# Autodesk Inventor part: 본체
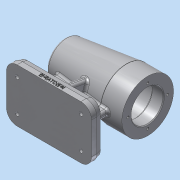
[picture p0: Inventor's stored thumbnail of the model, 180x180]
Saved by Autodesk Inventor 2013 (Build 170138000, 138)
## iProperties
Created: 2017-01
Part Number: 본체
Material: 알루미늄 6061
Document SubType Name: Modeling
Designer: dgall
Density: 2.71 g/cm^3
Mass: 795.17 g
Surface Area: 661.852 cm^2
Volume: 293.421 cm^3
Author: dgall
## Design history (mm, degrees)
sketch "스케치1"
  geometry: L1 (-56, 0)-(56, 0); L2 (56, 0)-(56, 34); L3 (56, 34)-(28, 34); L4 (28, 34)-(-52.27, 24.144); L5 (56, 21)-(41, 21); L6 (41, 21)-(41, 24); L7 (41, 24)-(-13, 24); L8 (-13, 24)-(-13, 21); L9 (-13, 21)-(-25, 21); L10 (-25, 21)-(-25, 17.5); L11 (-25, 17.5)-(-43, 17.5); L12 (-43, 17.5)-(-43, 16); L13 (-43, 16)-(-47, 16); L14 (-47, 16)-(-47, 10.5); L15 (-47, 10.5)-(-50, 10.5); L16 (-50, 10.5)-(-50, 0); A1 r 80 centre (24, 0) between (-52.27, 24.144) and (-56, 0); 2 further points
  constraints: 32 end point, 10 parallel, 3 perpendicular, 2 collinear, 2 point on circle, 2 point on line, 1 centre point, 1 coincident, 1 horizontal, 1 horizontal alignment, 1 midpoint
  dimensions: "d0" = 112 distance of L1.start L1.end; "d2" = 68 diameter of L3 L1; "d3" = 80 radius of A1; "d4" = 7 deg angle of L4 L3; "d5" = 28 distance of L2.end L3.end; "d6" = 48 diameter of L7 L1; "d7" = 42 diameter of L5 L1; "d9" = 35 diameter of L11 L1; "d10" = 32 diameter of L13 L1; "d11" = 21 diameter of L15 L1; "d12" = 15 distance of L5.start L5.end; "d13" = 54 distance of L6.end L7.end; "d14" = 3 distance of L14.end L15.end; "d15" = 4 distance of L12.end L13.end; "d16" = 18 distance of L10.end L11.end; "d17" = 12 distance of L8.end L9.end
revolve "회전1" sketch "스케치1" stored, may be unused: angle "d18" = 90 deg
node "작업 평면1"
sketch "스케치2"
  geometry: L1 (-56, 34)-(-56, -34) reference; L2 (-56, -35)-(56, -35); L3 (56, -35)-(56, 35); L4 (56, 35)-(-56, 35); L5 (-56, 35)-(-56, -35); 2 further points
  constraints: 8 end point, 2 parallel, 1 collinear, 1 horizontal, 1 horizontal alignment, 1 midpoint, 1 perpendicular
  dimensions: "d20" = 112 distance of L2.start L2.end; "d22" = 70 distance of L4.end L2.start
extrude "돌출1" join sketch "스케치2" distance "d23" = 7; taper "d24" = 0 deg
fillet "모깎기1" dims "d25" = 14
sketch "스케치3"
  geometry: L1 (42, 35)-(-42, 35) reference; L2 (-56, 21)-(-56, -21) reference; L3 (-42, -35)-(42, -35) reference; L4 (56, -21)-(56, 21) reference; A1 r 14 centre (42, 21) between (56, 21) and (42, 35) reference; A2 r 14 centre (-42, 21) between (-42, 35) and (-56, 21) reference; A3 r 14 centre (-42, -21) between (-56, -21) and (-42, -35) reference; A4 r 14 centre (42, -21) between (42, -35) and (56, -21) reference; 1 further point
extrude "돌출2" join sketch "스케치3" distance "d26" = 7; taper "d27" = -15 deg
sketch "스케치4"
  geometry: L1 (-74, -35)-(-74, 35) reference; L2 (-74, 35)-(-67, 35) reference; L3 (-67, 35)-(-60, 33.124) reference; L4 (-60, 33.124)-(-60, -33.124) reference; L5 (-60, -33.124)-(-67, -35) reference; L6 (-67, -35)-(-74, -35) reference; L7 (-18.211, 15.632)-(-60, 23); L8 (-18.211, -15.632)-(-60, -23); C1 r 30.562 at (0, 0) reference; A1 r 24 centre (0, 0) between (-18.211, 15.632) and (-18.211, -15.632) reference; 1 further point
  constraints: 4 end point, 2 point on circle, 2 point on line, 1 equal length
  dimensions: "d30" = 100 deg angle of L4 L7; "d31" = 100 deg angle of L4 L8; "d32" = 12 distance from line of L2 L7.end
extrude "돌출3" join sketch "스케치4" stored distance "d33" = 8; taper "d34" = 0 deg
sketch "스케치5"
  geometry: L1 (56, -74)-(-56, -74) reference; L2 (-56, -74)-(-56, -67) reference; L3 (-56, -67)-(-54.124, -60) reference; L4 (-54.124, -60)-(-4, -60) reference; L5 (-4, -60)-(-4, -30.071) reference; L6 (-4, -30.071)-(-52.27, -24.144) reference; L7 (-52.27, 24.144)-(28, 34) reference; L8 (28, 34)-(56, 34) reference; L9 (56, 34)-(56, 21) reference; L10 (56, 21)-(41, 21) reference; L11 (41, 21)-(41, 24) reference; L12 (41, 24)-(-13, 24) reference; L13 (-13, 24)-(-13, 21) reference; L14 (-13, 21)-(-25, 21) reference; L15 (-25, 21)-(-25, 17.5) reference; L16 (-25, 17.5)-(-43, 17.5) reference; L17 (-43, 17.5)-(-43, 16) reference; L18 (-43, 16)-(-47, 16) reference; L19 (-47, 16)-(-47, 10.5) reference; L20 (-47, 10.5)-(-50, 10.5) reference; L21 (-50, 10.5)-(-50, -10.5) reference; L22 (-50, -10.5)-(-47, -10.5) reference; L23 (-47, -10.5)-(-47, -16) reference; L24 (-47, -16)-(-43, -16) reference; L25 (-43, -16)-(-43, -17.5) reference; L26 (-43, -17.5)-(-25, -17.5) reference; L27 (-25, -17.5)-(-25, -21) reference; L28 (-25, -21)-(-13, -21) reference; L29 (-13, -21)-(-13, -24) reference; L30 (-13, -24)-(41, -24) reference; L31 (41, -24)-(41, -21) reference; L32 (41, -21)-(56, -21) reference; L33 (56, -21)-(56, -34) reference; L34 (56, -34)-(28, -34) reference; L35 (28, -34)-(4, -31.053) reference; L36 (4, -31.053)-(4, -60) reference; L37 (4, -60)-(54.124, -60) reference; L38 (54.124, -60)-(56, -67) reference; L39 (56, -67)-(56, -74) reference; L40 (-38, -25.896)-(-38, -60); L41 (38, -34)-(38, -60); A1 r 80 centre (24, 0) between (-52.27, 24.144) and (-52.27, -24.144) reference; 1 further point
  constraints: 4 end point, 4 point on line, 2 perpendicular
  dimensions: "d35" = 18 distance between parallel lines of L2 L40; "d36" = 18 distance between parallel lines of L39 L41
  node "절단 모서리 투영2"
feature "리브1" dims "d37" = 1, "d38" = 8, "d39" = 0, "d40" = 0, "d41" = 1, "d42" = 1
feature "리브2" dims "d43" = 1, "d44" = 8, "d45" = 0, "d46" = 0, "d47" = 1, "d48" = 1
sketch "스케치6" dims "d49" = 5
  geometry: L1 (-39.113, 26)-(-36.226, 21); L2 (-36.226, 21)-(-39.113, 16); L3 (-39.113, 16)-(-44.887, 16); L4 (-44.887, 16)-(-47.774, 21); L5 (-47.774, 21)-(-44.887, 26); L6 (-44.887, 26)-(-39.113, 26); L7 (-39.113, -16)-(-36.226, -21); L8 (-36.226, -21)-(-39.113, -26); L9 (-39.113, -26)-(-44.887, -26); L10 (-44.887, -26)-(-47.774, -21); L11 (-47.774, -21)-(-44.887, -16); L12 (-44.887, -16)-(-39.113, -16); L13 (44.887, -16)-(47.774, -21); L14 (47.774, -21)-(44.887, -26); L15 (44.887, -26)-(39.113, -26); L16 (39.113, -26)-(36.226, -21); L17 (36.226, -21)-(39.113, -16); L18 (39.113, -16)-(44.887, -16); L19 (44.887, 26)-(47.774, 21); L20 (47.774, 21)-(44.887, 16); L21 (44.887, 16)-(39.113, 16); L22 (39.113, 16)-(36.226, 21); L23 (36.226, 21)-(39.113, 26); L24 (39.113, 26)-(44.887, 26); A1 r 12.124 centre (-42, -21) between (-54.124, -21) and (-42, -33.124) reference; A2 r 12.124 centre (42, -21) between (42, -33.124) and (54.124, -21) reference; A3 r 12.124 centre (42, 21) between (54.124, 21) and (42, 33.124) reference; A4 r 12.124 centre (-42, 21) between (-42, 33.124) and (-54.124, 21) reference; 13 further points
  constraints: 48 end point, 8 coincident, 8 vertical alignment, 4 midpoint, 60 other
extrude "돌출4" cut sketch "스케치6" distance "d51" = 4; taper "d52" = 0 deg
sketch "스케치7"
  geometry: A1 r 14 centre (-42, -21) between (-56, -21) and (-42, -35) reference; A2 r 14 centre (42, -21) between (42, -35) and (56, -21) reference; A3 r 14 centre (42, 21) between (56, 21) and (42, 35) reference; A4 r 14 centre (-42, 21) between (-42, 35) and (-56, 21) reference; 1 further point
hole "구멍1" sketch "스케치7" at (-42, 21), (-42, -21), (42, 21), (42, -21) diameter "d53" = 5; stored, may be unused: countersink angle "d57" = 90 deg, drill point angle "d59" = 118 deg; dims "d54" = 6, "d55" = 4, "d56" = 2, "d58" = 14
fillet "모깎기2" dims "d60" = 1
fillet "모깎기3" dims "d61" = 3
fillet "모깎기4" dims "d62" = 3
fillet "모깎기5" dims "d63" = 0.3
sketch "스케치8"
  geometry: L1 (98, 0)-(98, 7) reference; L2 (98, 0)-(84, 0) reference; 2 further points
  constraints: 1 other
  dimensions: "d64" = 56 distance from line of L1 point (42, 4); "d65" = 4 distance from line of L2 point (42, 4)
extrude "돌출5" join sketch "스케치8" distance "d66" = 0.5; taper "d67" = 0 deg
sketch "스케치9"
  geometry: C1 r 34 at (0, 0) reference; 1 further point
  constraints: 1 vertical alignment
  dimensions: "d68" = 26 distance of C1.centre point (0, 26)
hole "구멍2" sketch "스케치9" at (0, 26) diameter "d69" = 3.242; stored, may be unused: countersink angle "d73" = 90 deg, drill point angle "d75" = 118 deg; dims "d70" = 8, "d71" = 4, "d72" = 2, "d74" = 11
chamfer "모따기1" distance "d79" = 1; stored, may be unused: second distance "d80" = 2, angle "d81" = 45 deg
node "솔리드1"
pattern_circular "원형 패턴1" dims angle "d77" = 360 deg
node "절단 모서리 투영1"
other parameters: "d19" = -74
